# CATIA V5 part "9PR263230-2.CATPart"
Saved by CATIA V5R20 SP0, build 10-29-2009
Part number: 9PR263230-2
Revision: ANY
Definition: UNKNOWN
Nomenclature: 9PR263230-2
Source: Unknown
Bounding box of the stored display mesh (mm): x 0 to 30, y -12.803 to 12.803, z -13 to 13
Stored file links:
  C:\Users\Utente\Desktop\IO LAVORO\3D X SITO CF\CUMSA\3D files PR.233230\PR 263230\9PR263230-2.CATPart
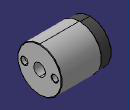
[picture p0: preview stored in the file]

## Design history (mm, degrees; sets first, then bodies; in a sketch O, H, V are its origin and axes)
Body1 "Cortar-Extruir5" (main body)
  Solid1: solid without history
